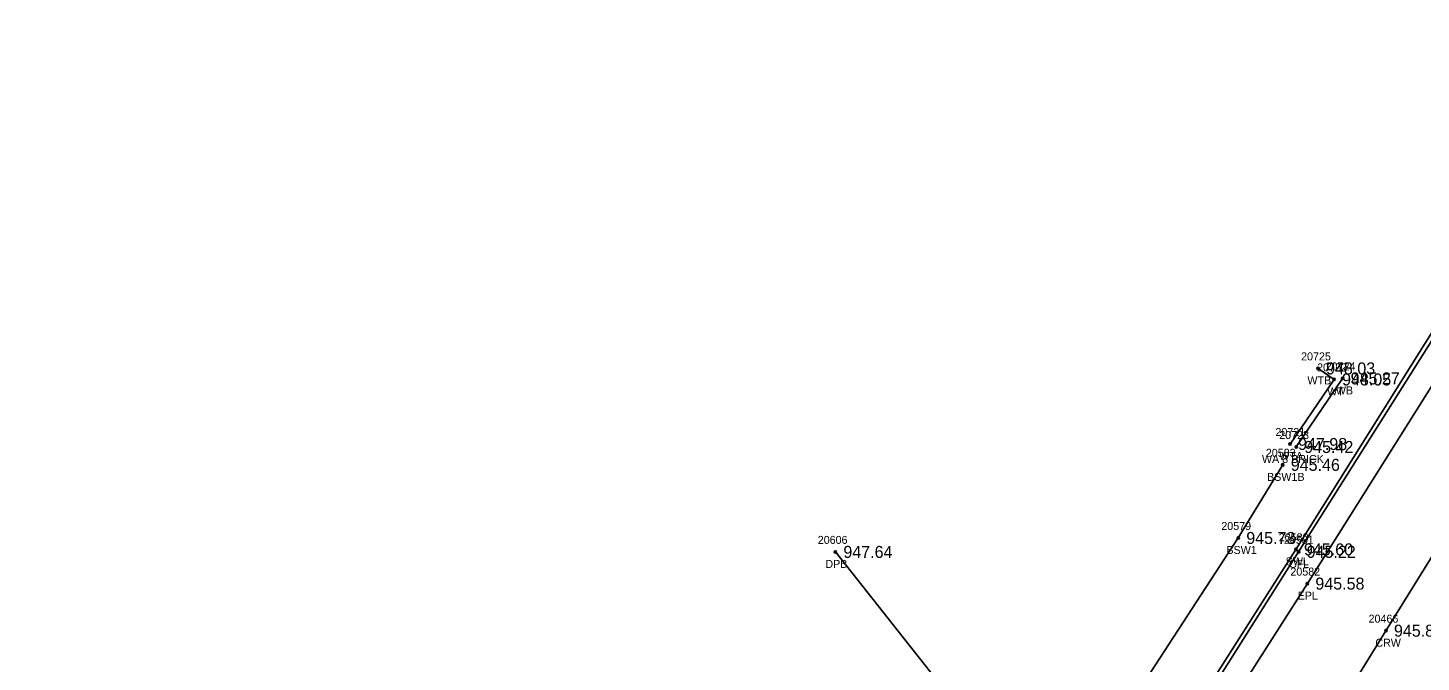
# Model space of a CAD drawing. Extents: x 1576181 to 1577685, y 1099396 to 1101490.
# Drawn here: x 1576353 to 1576527.1, y 1099766.9 to 1099846.2 of the extents above; entities that cross this region are included whole.
import ezdxf

# ---------------------------------------------------------------- set-up
doc = ezdxf.new("R2010")
doc.units = 0
for name, color, linetype in [('RD_DTM_BkLn1', 7, 'Continuous'), ('RD_DTM_BkLn2', 7, 'Continuous'), ('RD_EX_BldgApp', 7, 'Continuous'), ('RD_EX_Conc', 7, 'Continuous'), ('RD_EX_Conc_txCode', 7, 'Continuous'), ('RD_EX_Driveway', 7, 'Continuous'), ('RD_EX_Driveway_txCode', 7, 'Continuous'), ('RD_EX_Misc_txCode', 7, 'Continuous'), ('RD_EX_Road', 7, 'Continuous'), ('RD_EX_Road_txCode', 7, 'Continuous'), ('RD_EX_TX_Conc_ELEV', 7, 'Continuous'), ('RD_EX_TX_Driveway_ELEV', 7, 'Continuous'), ('RD_EX_TX_Misc_ELEV', 7, 'Continuous'), ('RD_EX_TX_Road_ELEV', 7, 'Continuous'), ('RD_HC_Survey_ELEV', 7, 'Continuous'), ('RD_HC_Survey_txCode', 7, 'Continuous'), ('RD_SMD_Locator', 7, 'Continuous')]:
    doc.layers.add(name, color=color, linetype=linetype)

msp = doc.modelspace()

# ---------------------------------------------------------------- linework, layer by layer
at = {"layer": 'RD_DTM_BkLn1'}
msp.add_lwpolyline([(1576435.96, 1099635.47), (1576469.98, 1099685.91), (1576496.51, 1099728.46), (1576522.67, 1099770.85), (1576549.06, 1099813.4), (1576563.36, 1099837.2), (1576575.09, 1099855.95), (1576600.75, 1099898.96), (1576625.57, 1099942.14), (1576652.37, 1099988.91), (1576675.03, 1100029.12), (1576699.51, 1100072.44), (1576723.52, 1100115.7), (1576748.08, 1100158.53), (1576774.13, 1100203.85), (1576797.97, 1100246.52), (1576822.46, 1100289.82), (1576846.93, 1100333.35), (1576871.37, 1100376.46), (1576888.27, 1100406.22)], dxfattribs=at)
at = {"layer": 'RD_DTM_BkLn2'}
msp.add_lwpolyline([(1576510.69, 1099794.17), (1576516.19, 1099802.24), (1576514.19, 1099803.62)], dxfattribs=at)
at = {"layer": 'RD_EX_BldgApp'}
msp.add_line((1576511.46, 1099793.8), (1576517.26, 1099802.37), dxfattribs=at)
at = {"layer": 'RD_EX_Conc'}
for points in [[(1576435.66, 1099661.47), (1576443.54, 1099673.97), (1576443.97, 1099673.78), (1576456.79, 1099694.01), (1576456.14, 1099694.19), (1576458.58, 1099697.76), (1576467.89, 1099712.42), (1576470.32, 1099716.02), (1576470.74, 1099715.71), (1576484.32, 1099737.29), (1576483.81, 1099737.74), (1576485.99, 1099741.1), (1576511.43, 1099781.01), (1576536.53, 1099821.05), (1576540.61, 1099827.59), (1576541.13, 1099827.37), (1576542.92, 1099831.85), (1576542.87, 1099835.12), (1576541.33, 1099839.59)], [(1576484.32, 1099737.29), (1576511.76, 1099780.7), (1576536.95, 1099820.66), (1576541.42, 1099827.15)], [(1576428.78, 1099665.98), (1576430.97, 1099669.47), (1576436.58, 1099677.8), (1576451.87, 1099701.45), (1576452.14, 1099701.9), (1576461.49, 1099716.63), (1576461.87, 1099717.2), (1576479.6, 1099744.71), (1576479.96, 1099745.23), (1576504.22, 1099782.43), (1576509.78, 1099791.57)]]:
    msp.add_lwpolyline(points, dxfattribs=at)
at = {"layer": 'RD_EX_Driveway'}
msp.add_line((1576467.04, 1099764.05), (1576453.88, 1099780.69), dxfattribs=at)
at = {"layer": 'RD_EX_Road'}
msp.add_lwpolyline([(1576217.78, 1099763.81), (1576263.48, 1099736.46), (1576283.45, 1099724.57), (1576282.38, 1099722.88), (1576302.5, 1099710.8), (1576345.46, 1099684.21), (1576368.62, 1099668.36), (1576383.76, 1099654.94), (1576386.09, 1099656.79), (1576408.06, 1099639.92), (1576408.06, 1099639.92), (1576411.91, 1099642.96), (1576420.57, 1099654.58), (1576428.78, 1099665.98), (1576435.66, 1099661.47), (1576436.12, 1099661.14), (1576438.46, 1099659.42), (1576459.37, 1099692.41), (1576486.6, 1099735.59), (1576512.85, 1099776.73), (1576539.46, 1099818.98), (1576543.78, 1099825.47), (1576541.42, 1099827.15), (1576542.92, 1099831.85)], dxfattribs=at)
at = {"layer": 'RD_SMD_Locator'}
for centre in [(1576514.19, 1099803.62), (1576516.19, 1099802.24), (1576517.26, 1099802.37), (1576510.69, 1099794.17), (1576511.46, 1099793.8), (1576509.78, 1099791.57), (1576504.22, 1099782.43), (1576511.43, 1099781.01), (1576453.88, 1099780.69), (1576511.76, 1099780.7), (1576512.85, 1099776.73), (1576522.67, 1099770.85)]:
    msp.add_circle(centre, 0.15, dxfattribs=at)

# ---------------------------------------------------------------- texts
at = {"layer": 'RD_EX_Conc_txCode'}
for s, p in [('20583', (1576507.66, 1099792.57)), ('BSW1B', (1576507.82, 1099789.57)), ('20579', (1576502.1, 1099783.43)), ('20580', (1576509.28, 1099782.01)), ('20581', (1576509.92, 1099781.7)), ('BSW1', (1576502.74, 1099780.43)), ('SWL', (1576510.14, 1099779.01)), ('CFL', (1576510.55, 1099778.7))]:
    msp.add_text(s, height=1, dxfattribs=at).set_placement(p)
at = {"layer": 'RD_EX_Driveway_txCode'}
for s, p in [('20606', (1576451.68, 1099781.69)), ('DPB', (1576452.63, 1099778.69))]:
    msp.add_text(s, height=1, dxfattribs=at).set_placement(p)
at = {"layer": 'RD_EX_Misc_txCode'}
for s, p in [('20725', (1576512.07, 1099804.62)), ('20722', (1576514.07, 1099803.24)), ('20724', (1576515.14, 1099803.37)), ('WTB', (1576512.86, 1099801.62)), ('WT', (1576515.33, 1099800.24)), ('WB', (1576516.41, 1099800.37)), ('20721', (1576508.86, 1099795.17)), ('20723', (1576509.34, 1099794.8)), ('WTA', (1576509.34, 1099792.17)), ('WA 8 BRICK', (1576507.18, 1099791.8))]:
    msp.add_text(s, height=1, dxfattribs=at).set_placement(p)
at = {"layer": 'RD_EX_Road_txCode'}
for s, p in [('20582', (1576510.73, 1099777.73)), ('EPL', (1576511.64, 1099774.73))]:
    msp.add_text(s, height=1, dxfattribs=at).set_placement(p)
at = {"layer": 'RD_EX_TX_Conc_ELEV'}
for s, p in [('945.46', (1576510.78, 1099790.82)), ('945.73', (1576505.22, 1099781.68)), ('945.60', (1576512.43, 1099780.26)), ('945.22', (1576512.76, 1099779.95))]:
    msp.add_text(s, height=1.5, dxfattribs=at).set_placement(p)
at = {"layer": 'RD_EX_TX_Driveway_ELEV'}
msp.add_text('947.64', height=1.5, dxfattribs=at).set_placement((1576454.88, 1099779.94))
at = {"layer": 'RD_EX_TX_Misc_ELEV'}
for s, p in [('948.03', (1576515.19, 1099802.87)), ('948.05', (1576517.19, 1099801.49)), ('945.27', (1576518.26, 1099801.62)), ('947.98', (1576511.69, 1099793.42)), ('945.42', (1576512.46, 1099793.05))]:
    msp.add_text(s, height=1.5, dxfattribs=at).set_placement(p)
at = {"layer": 'RD_EX_TX_Road_ELEV'}
msp.add_text('945.58', height=1.5, dxfattribs=at).set_placement((1576513.85, 1099775.98))
at = {"layer": 'RD_HC_Survey_ELEV'}
msp.add_text('945.85', height=1.5, dxfattribs=at).set_placement((1576523.67, 1099770.1))
at = {"layer": 'RD_HC_Survey_txCode'}
for s, p in [('20466', (1576520.5, 1099771.85)), ('CRW', (1576521.35, 1099768.85))]:
    msp.add_text(s, height=1, dxfattribs=at).set_placement(p)

doc.saveas('drawing.dxf')
